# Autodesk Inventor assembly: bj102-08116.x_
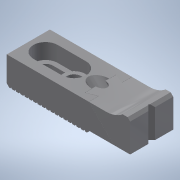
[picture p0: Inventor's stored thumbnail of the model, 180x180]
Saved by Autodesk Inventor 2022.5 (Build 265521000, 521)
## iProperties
Part Number: bj102-08116.x_
Material: 一般
Document SubType Name: Assembly
Designer: ImaoCorp
Sending System: SOLIDWORKS 2017-2017317
MC: AMD64
MC_MODEL: Intel64 Family 6 Model 60 Stepping 3, GenuineIntel
OS: Windows_NT
FRU: Parasolid Version 29.0, build 201,  4-17-2017
FORMAT: text
GUISE: transmit
KEY: bj102-08116
FILE: bj102-08116.x_t
DATE: Fri Mar 15 10:32:37 2019
Author: ImaoCorp
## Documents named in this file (4)
- X:\14_SW2022-Inv2022\00_全2023-1023新製品(TCC)まで\b\bj102-08116\BJ102-08116.iam
- X:\14_SW2022-Inv2022\00_全2023-1023新製品(TCC)まで\b\bj102-08116\bj102-08116_01.ipt
- X:\14_SW2022-Inv2022\00_全2023-1023新製品(TCC)まで\b\bj102-08116\bj102-08116_02.ipt
- X:\14_SW2022-Inv2022\00_全2023-1023新製品(TCC)まで\b\bj102-08116\bj102-08116_03.ipt
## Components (3 placed, 3 different names)
1. bj102-08116_01
2. bj102-08116_02
3. bj102-08116_03
